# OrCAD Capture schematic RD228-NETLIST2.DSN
size A3
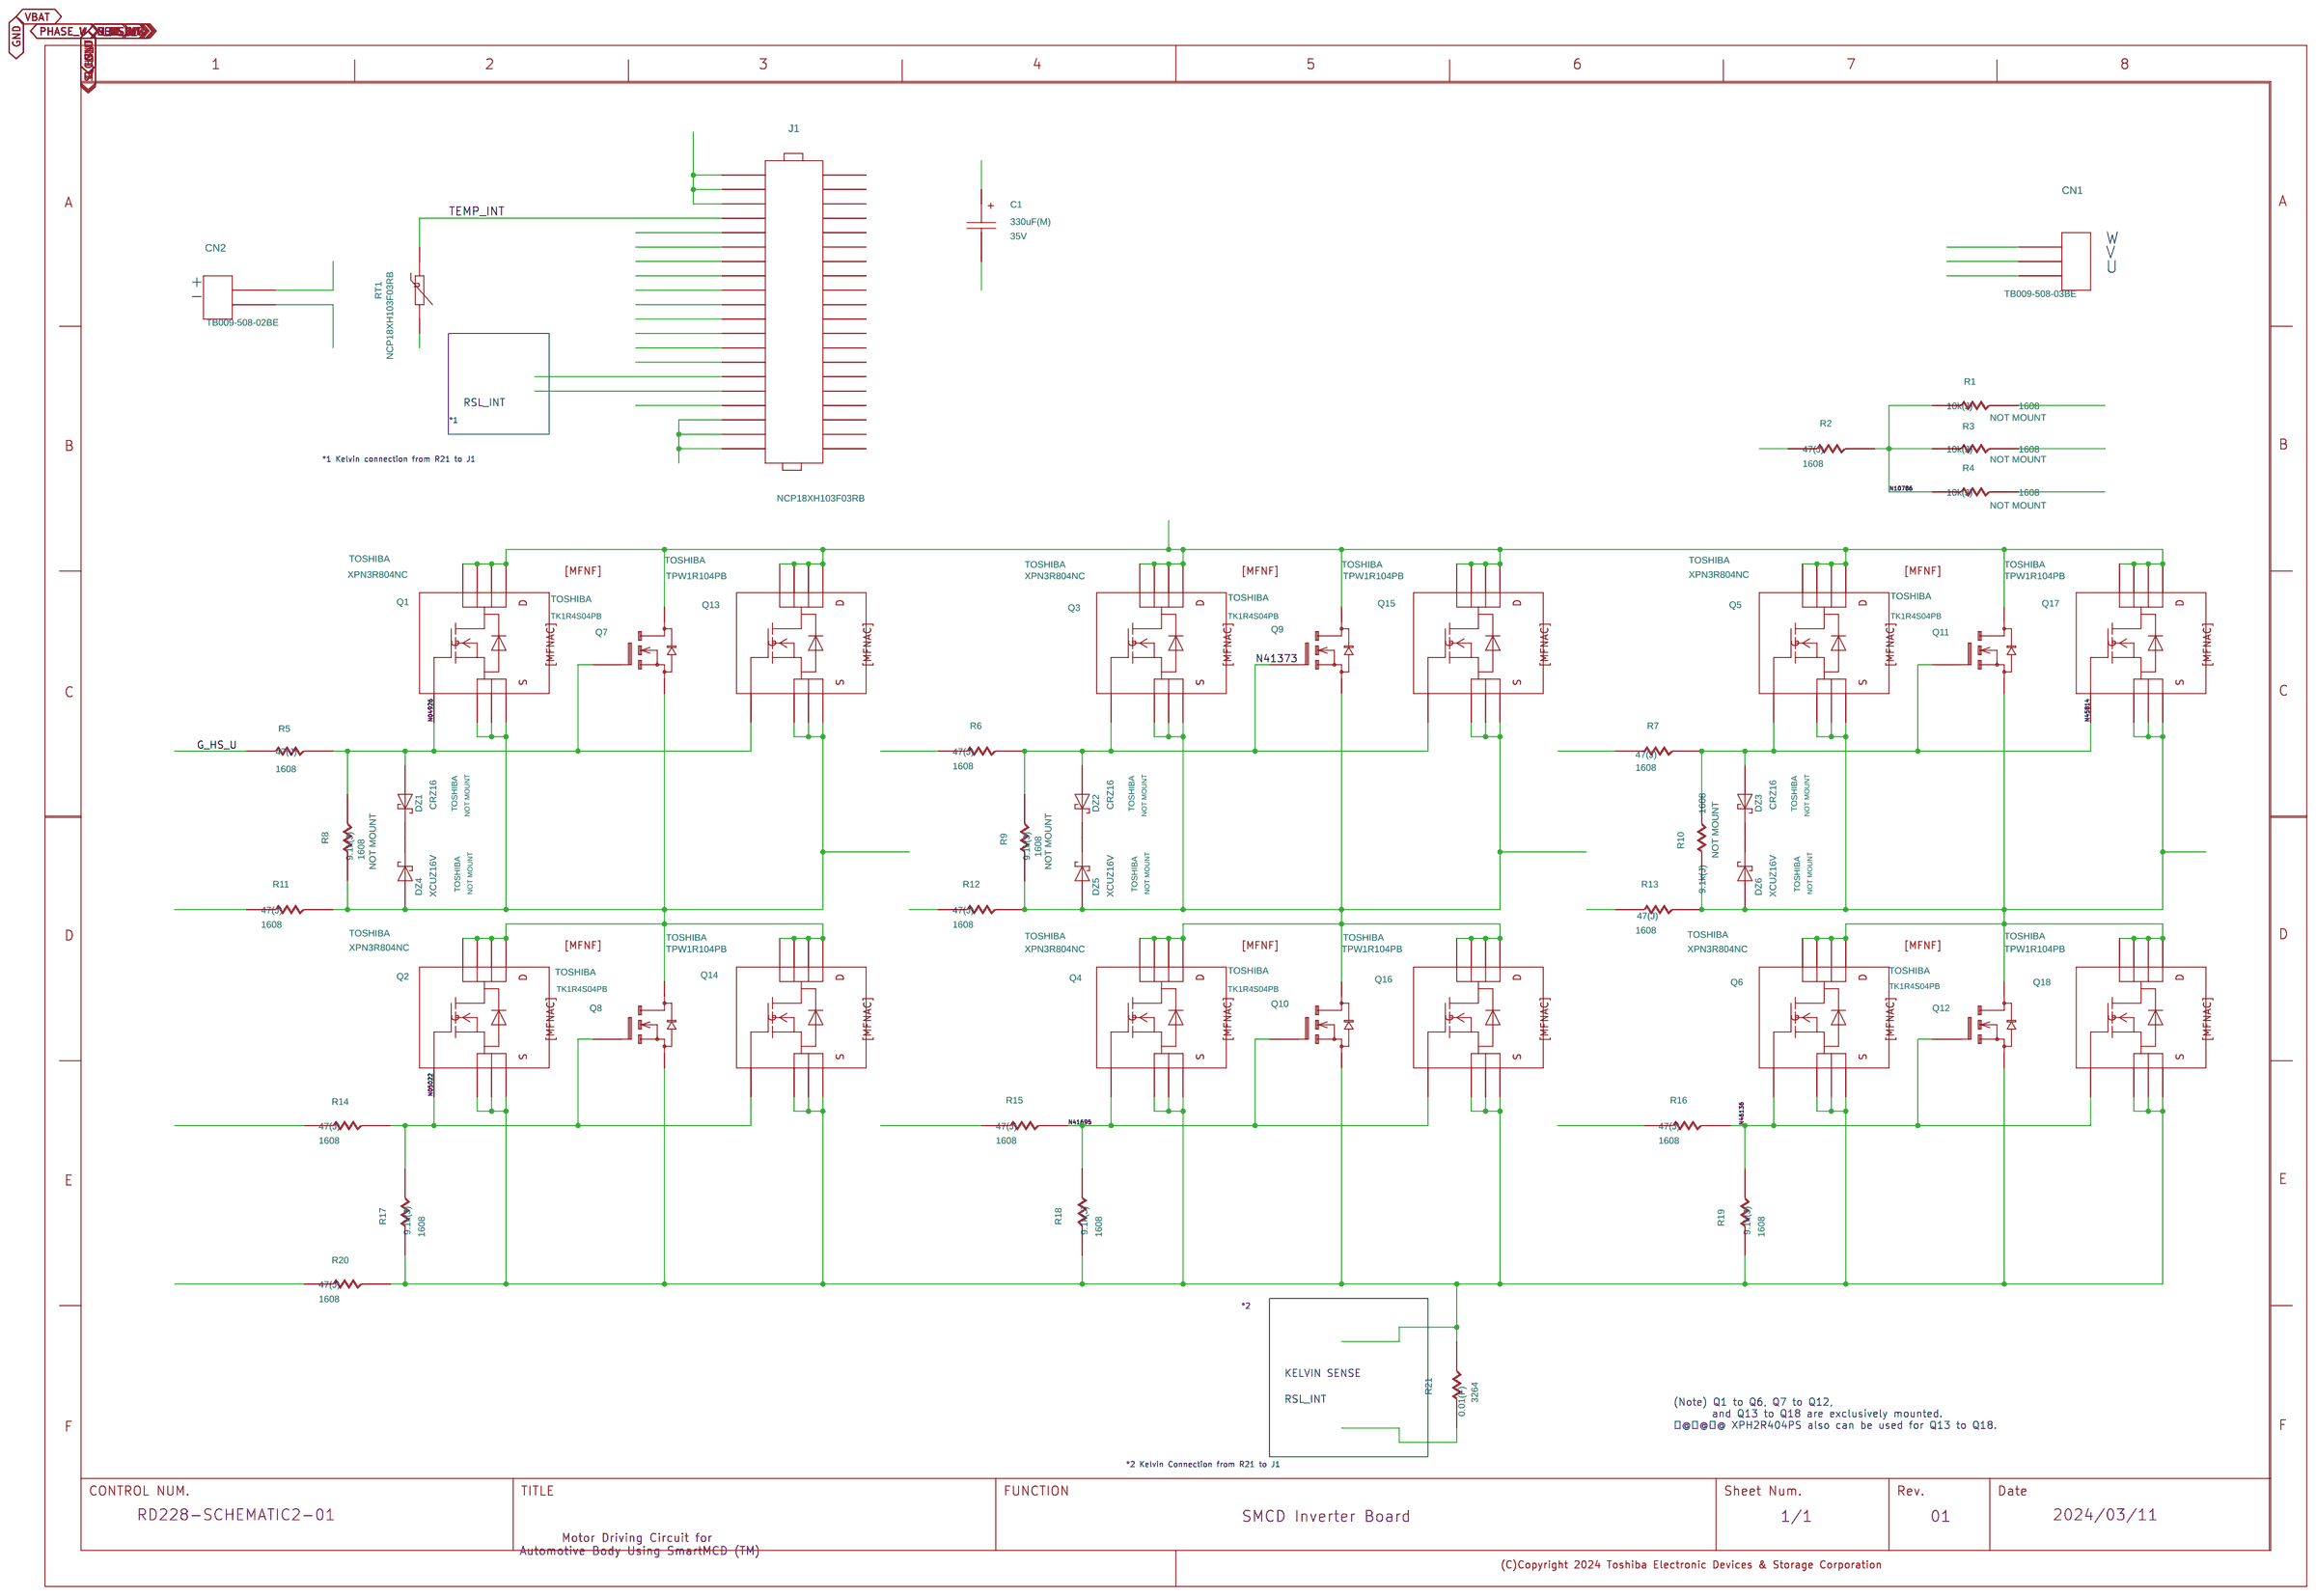
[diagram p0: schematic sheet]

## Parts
C1  CP
CN1  SCREW TERMINAL 3P
CN2  SCREW TERMINAL 2P
DZ1  SBD
DZ2  SBD
DZ3  SBD
DZ4  SBD
DZ5  SBD
DZ6  SBD
J1  CONN PCB 20x2
Q1  MFNAC
Q2  MFNAC
Q3  MFNAC
Q4  MFNAC
Q5  MFNAC
Q6  MFNAC
Q7  MFNF
Q8  MFNF
Q9  MFNF
Q10  MFNF
Q11  MFNF
Q12  MFNF
Q13  MFNAC
Q14  MFNAC
Q15  MFNAC
Q16  MFNAC
Q17  MFNAC
Q18  MFNAC
R1  R
R2  R
R3  R
R4  R
R5  R
R6  R
R7  R
R8  R
R9  R
R10  R
R11  R
R12  R
R13  R
R14  R
R15  R
R16  R
R17  R
R18  R
R19  R
R20  R
R21  R
RT1  VARA
U3  WAKU_DEF100

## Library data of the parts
C1 = CP: CAPACITANCETOLE: M; CDMASTERCADCELG: DC213N; CHIPSIZE: D35xL30; COMP: PRT_4; COMPONENTNAME: CP_CP; COMPONENTTYPE: 4; FNLEADFREETHET1GT2GMCTH1: 9_N_N; GCOUNT: 1; INSTANCENAME: INS16733; LAYOUTNAME: Z-4fe26e2d-0314-4a28-872c-3bd199d55978.cmp38; MAKER: RUBYCON; MAXGCOUNT: 1; NOMINALCAPACITA: 330u; OUMECLASSIFICATION: ƒAƒ‹ƒ~“d‰ðƒRƒ“ƒfƒ“ƒT; OUMEMAKER: SIT ƒ‹ƒrƒRƒ“; OUMEMAKERKATAMEI: 450MXC330M35X40; OUMEPARTTYPE: C; QUADMODEL: CON_330U; RATEDVOLTAGE: 450; SIZECODESMD: DIP; VAL1: 330uF(M); VAL2: 35V; VAL3: EEE-FN1V331UP; VAL4: Panasonic
CN1 = CON3: COMPONENTNAME: CON3_CON3; COMPONENTTYPE: 4; INSTANCENAME: INS12037; LAYOUTNAME: Z-4fe26e2d-0314-4a28-872c-3bd199d55978.cmp14; VAL3: TB009-508-03BE; VAL4: CUI Devices
CN2 = CON2: COMP: TB009-508-02BE; COMPONENTNAME: CON2_CON2; COMPONENTTYPE: 4; INSTANCENAME: INS65872; LAYOUTNAME: Z-4fe26e2d-0314-4a28-872c-3bd199d55978.cmp16; VAL4: CUI Devices
DZ1-DZ3 = SBD: AUTHOR: ikeda-k; COMPONENTKIND: 0; COMPONENTNAME: SBD_SBD; COMPONENTTYPE: 4; DATE: 2003/02/07; INSTANCENAME: INS75512; MAKER: TOSHIBA; NOTMOUNT: NOT MOUNT; NUMBER DEVICES IN PACKAGE: 1; PIN NAMES ROTATE: True; PIN NAMES VISIBLE: False; PIN NUMBERS VISIBLE: True; TIME: 14:49:55; UPDATEDATE: 2006/10/04; UPDATETIME: 08:16:22; UPDATEUSER: fukuda-y; USERCOMPTEXT3: TOSHIBA; VAL3: CRZ16; VAL4: TOSHIBA
DZ4-DZ6 = SBD: AUTHOR: ikeda-k; COMPONENTKIND: 0; COMPONENTNAME: SBD_SBD; COMPONENTTYPE: 4; DATE: 2003/02/07; INSTANCENAME: INS75524; MAKER: TOSHIBA; NOTMOUNT: NOT MOUNT; NUMBER DEVICES IN PACKAGE: 1; PIN NAMES ROTATE: True; PIN NAMES VISIBLE: False; PIN NUMBERS VISIBLE: True; TIME: 14:49:55; UPDATEDATE: 2006/10/04; UPDATETIME: 08:16:22; UPDATEUSER: fukuda-y; USERCOMPTEXT3: TOSHIBA; VAL3: XCUZ16V; VAL4: TOSHIBA
J1 = CONN_PCB_20X2_0: COMP: NCP18XH103F03RB; COMPONENTNAME: CONN_PCB_20x2_0_CONN_PCB_20x2_0; COMPONENTTYPE: 4; INSTANCENAME: INS11476; LAYOUTNAME: Z-4fe26e2d-0314-4a28-872c-3bd199d55978.cmp27; UPDATEDATE: 2024/2/16; UPDATETIME: 13:16:52; VAL3: 7-534206-0; VAL4: TE Connectivity
Q1 = MFNAC: COMP: PRT_67; COMPONENTNAME: MFNAC_MFNAC; COMPONENTTYPE: 4; INSTANCENAME: INS28653; LAYOUTNAME: Z-4fe26e2d-0314-4a28-872c-3bd199d55978.cmp44; MAKER: TOSHIBA; USERCOMPTEXT3: TOSHIBA; VAL3: XPN3R804NC; VAL4: TOSHIBA
Q2 = MFNAC: COMP: PRT_67; COMPONENTNAME: MFNAC_MFNAC; COMPONENTTYPE: 4; INSTANCENAME: INS31297; LAYOUTNAME: Z-4fe26e2d-0314-4a28-872c-3bd199d55978.cmp3; MAKER: TOSHIBA; USERCOMPTEXT3: TOSHIBA; VAL3: XPN3R804NC; VAL4: TOSHIBA
Q3 = MFNAC: COMP: PRT_67; COMPONENTNAME: MFNAC_MFNAC; COMPONENTTYPE: 4; INSTANCENAME: INS41315; LAYOUTNAME: Z-4fe26e2d-0314-4a28-872c-3bd199d55978.cmp10; MAKER: TOSHIBA; USERCOMPTEXT3: TOSHIBA; VAL3: XPN3R804NC; VAL4: TOSHIBA
Q4 = MFNAC: COMP: PRT_67; COMPONENTNAME: MFNAC_MFNAC; COMPONENTTYPE: 4; INSTANCENAME: INS41637; LAYOUTNAME: Z-4fe26e2d-0314-4a28-872c-3bd199d55978.cmp23; MAKER: TOSHIBA; USERCOMPTEXT3: TOSHIBA; VAL3: XPN3R804NC; VAL4: TOSHIBA
Q5 = MFNAC: COMP: PRT_67; COMPONENTNAME: MFNAC_MFNAC; COMPONENTTYPE: 4; INSTANCENAME: INS45756; LAYOUTNAME: Z-4fe26e2d-0314-4a28-872c-3bd199d55978.cmp8; MAKER: TOSHIBA; USERCOMPTEXT3: TOSHIBA; VAL3: XPN3R804NC; VAL4: TOSHIBA
Q6 = MFNAC: COMP: PRT_67; COMPONENTNAME: MFNAC_MFNAC; COMPONENTTYPE: 4; INSTANCENAME: INS46078; LAYOUTNAME: Z-4fe26e2d-0314-4a28-872c-3bd199d55978.cmp21; MAKER: TOSHIBA; USERCOMPTEXT3: TOSHIBA; VAL3: XPN3R804NC; VAL4: TOSHIBA
Q7 = MFNF: COMPONENTNAME: MFNF_MFNF; COMPONENTTYPE: 4; INSTANCENAME: INS28533; LAYOUTNAME: Z-4fe26e2d-0314-4a28-872c-3bd199d55978.cmp32; MAKER: TOSHIBA; USERCOMPTEXT3: TOSHIBA; VAL3: TK1R4S04PB; VAL4: TOSHIBA
Q8 = MFNF: COMP: PRT_9; COMPONENTNAME: MFNF_MFNF; COMPONENTTYPE: 4; INSTANCENAME: INS31341; LAYOUTNAME: Z-4fe26e2d-0314-4a28-872c-3bd199d55978.cmp20; MAKER: TOSHIBA; USERCOMPTEXT3: TOSHIBA; VAL3: TK1R4S04PB; VAL4: TOSHIBA
Q9 = MFNF: COMP: PRT_9; COMPONENTNAME: MFNF_MFNF; COMPONENTTYPE: 4; INSTANCENAME: INS41359; LAYOUTNAME: Z-4fe26e2d-0314-4a28-872c-3bd199d55978.cmp31; MAKER: TOSHIBA; USERCOMPTEXT3: TOSHIBA; VAL3: TK1R4S04PB; VAL4: TOSHIBA
Q10 = MFNF: COMP: PRT_9; COMPONENTNAME: MFNF_MFNF; COMPONENTTYPE: 4; INSTANCENAME: INS41681; LAYOUTNAME: Z-4fe26e2d-0314-4a28-872c-3bd199d55978.cmp40; MAKER: TOSHIBA; USERCOMPTEXT3: TOSHIBA; VAL3: TK1R4S04PB; VAL4: TOSHIBA
Q11 = MFNF: COMP: PRT_9; COMPONENTNAME: MFNF_MFNF; COMPONENTTYPE: 4; INSTANCENAME: INS45800; LAYOUTNAME: Z-4fe26e2d-0314-4a28-872c-3bd199d55978.cmp29; MAKER: TOSHIBA; USERCOMPTEXT3: TOSHIBA; VAL3: TK1R4S04PB; VAL4: TOSHIBA
Q12 = MFNF: COMP: PRT_9; COMPONENTNAME: MFNF_MFNF; COMPONENTTYPE: 4; INSTANCENAME: INS46122; LAYOUTNAME: Z-4fe26e2d-0314-4a28-872c-3bd199d55978.cmp39; MAKER: TOSHIBA; USERCOMPTEXT3: TOSHIBA; VAL3: TK1R4S04PB; VAL4: TOSHIBA
Q13 = MFNAC: COMPCOMMENT: XPH2R404PS; COMPONENTNAME: MFNAC_MFNAC; COMPONENTTYPE: 4; INSTANCENAME: INS28724; LAYOUTNAME: Z-4fe26e2d-0314-4a28-872c-3bd199d55978.cmp30; MAKER: TOSHIBA; USERCOMPTEXT3: TOSHIBA; VAL3: TPW1R104PB; VAL4: TOSHIBA
Q14 = MFNAC: COMP: PRT_67; COMPCOMMENT: XPH2R404PS; COMPONENTNAME: MFNAC_MFNAC; COMPONENTTYPE: 4; INSTANCENAME: INS31319; LAYOUTNAME: Z-4fe26e2d-0314-4a28-872c-3bd199d55978.cmp12; MAKER: TOSHIBA; USERCOMPTEXT3: TOSHIBA; VAL3: TPW1R104PB; VAL4: TOSHIBA
Q15 = MFNAC: COMP: PRT_67; COMPCOMMENT: XPH2R404PS; COMPONENTNAME: MFNAC_MFNAC; COMPONENTTYPE: 4; INSTANCENAME: INS41337; LAYOUTNAME: Z-4fe26e2d-0314-4a28-872c-3bd199d55978.cmp26; MAKER: TOSHIBA; USERCOMPTEXT3: TOSHIBA; VAL3: TPW1R104PB; VAL4: TOSHIBA
Q16 = MFNAC: COMP: PRT_67; COMPCOMMENT: XPH2R404PS; COMPONENTNAME: MFNAC_MFNAC; COMPONENTTYPE: 4; INSTANCENAME: INS41659; LAYOUTNAME: Z-4fe26e2d-0314-4a28-872c-3bd199d55978.cmp34; MAKER: TOSHIBA; USERCOMPTEXT3: TOSHIBA; VAL3: TPW1R104PB; VAL4: TOSHIBA
Q17 = MFNAC: COMP: PRT_67; COMPCOMMENT: XPH2R404PS; COMPONENTNAME: MFNAC_MFNAC; COMPONENTTYPE: 4; INSTANCENAME: INS45778; LAYOUTNAME: Z-4fe26e2d-0314-4a28-872c-3bd199d55978.cmp22; MAKER: TOSHIBA; USERCOMPTEXT3: TOSHIBA; VAL3: TPW1R104PB; VAL4: TOSHIBA
Q18 = MFNAC: COMP: PRT_67; COMPCOMMENT: XPH2R404PS; COMPONENTNAME: MFNAC_MFNAC; COMPONENTTYPE: 4; INSTANCENAME: INS46100; LAYOUTNAME: Z-4fe26e2d-0314-4a28-872c-3bd199d55978.cmp33; MAKER: TOSHIBA; USERCOMPTEXT3: TOSHIBA; VAL3: TPW1R104PB; VAL4: TOSHIBA
R1 = R: ADSMODELNAME: s_RL1632H_R001_JN; CDMASTERCADCELG: KC0020; CHIPSIZE: 3216; COMP: PRT_5; COMPONENTNAME: R_R; COMPONENTTYPE: 4; FNLEADFREETHET1GT2GMCTH1: N_N_N; GCOUNT: 1; INSTANCENAME: INS10722; LAYOUTNAME: Z-4fe26e2d-0314-4a28-872c-3bd199d55978.cmp9; MAKER: KOA; MAXGCOUNT: 1; MOUNTINGFORMSMD: SMD; NOMINALRESISTAN: 1m; NOTMOUNT: NOT MOUNT; OUMECLASSIFICATION: \ÊÀpÅèïRí; OUMEMAKER: SSM iHÆ; OUMEMAKERKATAMEI: RL1632H-R001-JN; POWERRATING: 500m; QUADMODEL: RES_1M; RESISTANCETOLER: J; SIZECODESMD: 1608; VAL1: 10k(J); VAL2: 0.1W; VAL3: RK73B1ETTP103J; VAL4: KOA
R2 = R: ADSMODELNAME: s_RL1632H_R001_JN; CDMASTERCADCELG: KC0020; CHIPSIZE: 3216; COMP: PRT_5; COMPONENTNAME: R_R; COMPONENTTYPE: 4; FNLEADFREETHET1GT2GMCTH1: N_N_N; GCOUNT: 1; INSTANCENAME: INS10855; LAYOUTNAME: Z-4fe26e2d-0314-4a28-872c-3bd199d55978.cmp28; MAKER: KOA; MAXGCOUNT: 1; MOUNTINGFORMSMD: SMD; NOMINALRESISTAN: 1m; OUMECLASSIFICATION: \ÊÀpÅèïRí; OUMEMAKER: SSM iHÆ; OUMEMAKERKATAMEI: RL1632H-R001-JN; POWERRATING: 500m; QUADMODEL: RES_1M; RESISTANCETOLER: J; SIZECODESMD: 1608; VAL1: 47(J); VAL2: 0.1W; VAL3: RK73B1ETTP470J; VAL4: KOA
R3 = R: ADSMODELNAME: s_RL1632H_R001_JN; CDMASTERCADCELG: KC0020; CHIPSIZE: 3216; COMP: PRT_5; COMPONENTNAME: R_R; COMPONENTTYPE: 4; FNLEADFREETHET1GT2GMCTH1: N_N_N; GCOUNT: 1; INSTANCENAME: INS10744; LAYOUTNAME: Z-4fe26e2d-0314-4a28-872c-3bd199d55978.cmp24; MAKER: KOA; MAXGCOUNT: 1; MOUNTINGFORMSMD: SMD; NOMINALRESISTAN: 1m; NOTMOUNT: NOT MOUNT; OUMECLASSIFICATION: \ÊÀpÅèïRí; OUMEMAKER: SSM iHÆ; OUMEMAKERKATAMEI: RL1632H-R001-JN; POWERRATING: 500m; QUADMODEL: RES_1M; RESISTANCETOLER: J; SIZECODESMD: 1608; VAL1: 10k(J); VAL2: 0.1W; VAL3: RK73B1ETTP103J; VAL4: KOA
R4 = R: ADSMODELNAME: s_RL1632H_R001_JN; CDMASTERCADCELG: KC0020; CHIPSIZE: 3216; COMP: PRT_5; COMPONENTNAME: R_R; COMPONENTTYPE: 4; FNLEADFREETHET1GT2GMCTH1: N_N_N; GCOUNT: 1; INSTANCENAME: INS10766; LAYOUTNAME: Z-4fe26e2d-0314-4a28-872c-3bd199d55978.cmp35; MAKER: KOA; MAXGCOUNT: 1; MOUNTINGFORMSMD: SMD; NOMINALRESISTAN: 1m; NOTMOUNT: NOT MOUNT; OUMECLASSIFICATION: \ÊÀpÅèïRí; OUMEMAKER: SSM iHÆ; OUMEMAKERKATAMEI: RL1632H-R001-JN; POWERRATING: 500m; QUADMODEL: RES_1M; RESISTANCETOLER: J; SIZECODESMD: 1608; VAL1: 10k(J); VAL2: 0.1W; VAL3: RK73B1ETTP103J; VAL4: KOA
R5 = R: ADSMODELNAME: s_RL1632H_R001_JN; CDMASTERCADCELG: KC0020; CHIPSIZE: 3216; COMP: PRT_5; COMPONENTNAME: R_R; COMPONENTTYPE: 4; FNLEADFREETHET1GT2GMCTH1: N_N_N; GCOUNT: 1; INSTANCENAME: INS6200; LAYOUTNAME: Z-4fe26e2d-0314-4a28-872c-3bd199d55978.cmp25; MAKER: KOA; MAXGCOUNT: 1; MOUNTINGFORMSMD: SMD; NOMINALRESISTAN: 1m; OUMECLASSIFICATION: \ÊÀpÅèïRí; OUMEMAKER: SSM iHÆ; OUMEMAKERKATAMEI: RL1632H-R001-JN; POWERRATING: 500m; QUADMODEL: RES_1M; RESISTANCETOLER: J; SIZECODESMD: 1608; VAL1: 47(J); VAL2: 0.1W; VAL3: RK73B1JTTD470J; VAL4: KOA
R6 = R: ADSMODELNAME: s_RL1632H_R001_JN; CDMASTERCADCELG: KC0020; CHIPSIZE: 3216; COMP: PRT_5; COMPONENTNAME: R_R; COMPONENTTYPE: 4; FNLEADFREETHET1GT2GMCTH1: N_N_N; GCOUNT: 1; INSTANCENAME: INS41415; LAYOUTNAME: Z-4fe26e2d-0314-4a28-872c-3bd199d55978.cmp5; MAKER: KOA; MAXGCOUNT: 1; MOUNTINGFORMSMD: SMD; NOMINALRESISTAN: 1m; OUMECLASSIFICATION: \ÊÀpÅèïRí; OUMEMAKER: SSM iHÆ; OUMEMAKERKATAMEI: RL1632H-R001-JN; POWERRATING: 500m; QUADMODEL: RES_1M; RESISTANCETOLER: J; SIZECODESMD: 1608; VAL1: 47(J); VAL2: 0.1W; VAL3: RK73B1JTTD470J; VAL4: KOA
R7 = R: ADSMODELNAME: s_RL1632H_R001_JN; CDMASTERCADCELG: KC0020; CHIPSIZE: 3216; COMPONENTNAME: R_R; COMPONENTTYPE: 4; FNLEADFREETHET1GT2GMCTH1: N_N_N; GCOUNT: 1; INSTANCENAME: INS45856; LAYOUTNAME: Z-4fe26e2d-0314-4a28-872c-3bd199d55978.cmp4; MAKER: KOA; MAXGCOUNT: 1; MOUNTINGFORMSMD: SMD; NOMINALRESISTAN: 1m; OUMECLASSIFICATION: \ÊÀpÅèïRí; OUMEMAKER: SSM iHÆ; OUMEMAKERKATAMEI: RL1632H-R001-JN; POWERRATING: 500m; QUADMODEL: RES_1M; RESISTANCETOLER: J; SIZECODESMD: 1608; VAL1: 47(J); VAL2: 0.1W; VAL3: RK73B1JTTD470J; VAL4: KOA
R8 = R: ADSMODELNAME: s_RK73B1JTTD103J@@; CDMASTERCADCELG: KC0133; CHIPSIZE: 1608; COMP: PRT_8; COMPONENTNAME: R_R; COMPONENTTYPE: 4; FNLEADFREETHET1GT2GMCTH1: N_N_N; GCOUNT: 1; INSTANCENAME: INS8565; LAYOUTNAME: Z-4fe26e2d-0314-4a28-872c-3bd199d55978.cmp43; MAKER: KOA; MAXGCOUNT: 1; MOUNTINGFORMSMD: SMD; NOMINALRESISTAN: 10K; NOTMOUNT: NOT MOUNT; OUMECLASSIFICATION: \ÊÀpÅèïRí; OUMEMAKER: KOA R[A; OUMEMAKERKATAMEI: RK73B1JTTD103J@@; POWERRATING: 100m; QUADMODEL: RES_10K; RESISTANCETOLER: J; SIZECODESMD: 1608; VAL1: 9.1k(J); VAL2: 0.1W; VAL3: RK73B1ETTP912J; VAL4: KOA
R9 = R: ADSMODELNAME: s_RK73B1JTTD103J@@; CDMASTERCADCELG: KC0133; CHIPSIZE: 1608; COMP: PRT_8; COMPONENTNAME: R_R; COMPONENTTYPE: 4; FNLEADFREETHET1GT2GMCTH1: N_N_N; GCOUNT: 1; INSTANCENAME: INS41505; LAYOUTNAME: Z-4fe26e2d-0314-4a28-872c-3bd199d55978.cmp1; MAKER: KOA; MAXGCOUNT: 1; MOUNTINGFORMSMD: SMD; NOMINALRESISTAN: 10K; NOTMOUNT: NOT MOUNT; OUMECLASSIFICATION: \ÊÀpÅèïRí; OUMEMAKER: KOA R[A; OUMEMAKERKATAMEI: RK73B1JTTD103J@@; POWERRATING: 100m; QUADMODEL: RES_10K; RESISTANCETOLER: J; SIZECODESMD: 1608; VAL1: 9.1k(J); VAL2: 0.1W; VAL3: RK73B1ETTP912J; VAL4: KOA
R10 = R: ADSMODELNAME: s_RK73B1JTTD103J@@; CDMASTERCADCELG: KC0133; CHIPSIZE: 1608; COMP: PRT_8; COMPONENTNAME: R_R; COMPONENTTYPE: 4; FNLEADFREETHET1GT2GMCTH1: N_N_N; GCOUNT: 1; INSTANCENAME: INS45946; LAYOUTNAME: Z-4fe26e2d-0314-4a28-872c-3bd199d55978.cmp48; MAKER: KOA; MAXGCOUNT: 1; MOUNTINGFORMSMD: SMD; NOMINALRESISTAN: 10K; NOTMOUNT: NOT MOUNT; OUMECLASSIFICATION: \ÊÀpÅèïRí; OUMEMAKER: KOA R[A; OUMEMAKERKATAMEI: RK73B1JTTD103J@@; POWERRATING: 100m; QUADMODEL: RES_10K; RESISTANCETOLER: J; SIZECODESMD: 1608; VAL1: 9.1k(J); VAL2: 0.1W; VAL3: RK73B1ETTP912J; VAL4: KOA
R11 = R: ADSMODELNAME: s_RL1632H_R001_JN; CDMASTERCADCELG: KC0020; CHIPSIZE: 3216; COMP: PRT_5; COMPONENTNAME: R_R; COMPONENTTYPE: 4; FNLEADFREETHET1GT2GMCTH1: N_N_N; GCOUNT: 1; INSTANCENAME: INS6356; LAYOUTNAME: Z-4fe26e2d-0314-4a28-872c-3bd199d55978.cmp51; MAKER: KOA; MAXGCOUNT: 1; MOUNTINGFORMSMD: SMD; NOMINALRESISTAN: 1m; OUMECLASSIFICATION: \ÊÀpÅèïRí; OUMEMAKER: SSM iHÆ; OUMEMAKERKATAMEI: RL1632H-R001-JN; POWERRATING: 500m; QUADMODEL: RES_1M; RESISTANCETOLER: J; SIZECODESMD: 1608; VAL1: 47(J); VAL2: 0.1W; VAL3: RK73B1JTTD470J; VAL4: KOA
R12 = R: ADSMODELNAME: s_RL1632H_R001_JN; CDMASTERCADCELG: KC0020; CHIPSIZE: 3216; COMP: PRT_5; COMPONENTNAME: R_R; COMPONENTTYPE: 4; FNLEADFREETHET1GT2GMCTH1: N_N_N; GCOUNT: 1; INSTANCENAME: INS41533; LAYOUTNAME: Z-4fe26e2d-0314-4a28-872c-3bd199d55978.cmp13; MAKER: KOA; MAXGCOUNT: 1; MOUNTINGFORMSMD: SMD; NOMINALRESISTAN: 1m; OUMECLASSIFICATION: \ÊÀpÅèïRí; OUMEMAKER: SSM iHÆ; OUMEMAKERKATAMEI: RL1632H-R001-JN; POWERRATING: 500m; QUADMODEL: RES_1M; RESISTANCETOLER: J; SIZECODESMD: 1608; VAL1: 47(J); VAL2: 0.1W; VAL3: RK73B1JTTD470J; VAL4: KOA
R13 = R: ADSMODELNAME: s_RL1632H_R001_JN; CDMASTERCADCELG: KC0020; CHIPSIZE: 3216; COMP: PRT_5; COMPONENTNAME: R_R; COMPONENTTYPE: 4; FNLEADFREETHET1GT2GMCTH1: N_N_N; GCOUNT: 1; INSTANCENAME: INS45984; LAYOUTNAME: Z-4fe26e2d-0314-4a28-872c-3bd199d55978.cmp18; MAKER: KOA; MAXGCOUNT: 1; MOUNTINGFORMSMD: SMD; NOMINALRESISTAN: 1m; OUMECLASSIFICATION: \ÊÀpÅèïRí; OUMEMAKER: SSM iHÆ; OUMEMAKERKATAMEI: RL1632H-R001-JN; POWERRATING: 500m; QUADMODEL: RES_1M; RESISTANCETOLER: J; SIZECODESMD: 1608; VAL1: 47(J); VAL2: 0.1W; VAL3: RK73B1JTTD470J; VAL4: KOA
R14 = R: ADSMODELNAME: s_RL1632H_R001_JN; CDMASTERCADCELG: KC0020; CHIPSIZE: 3216; COMP: PRT_5; COMPONENTNAME: R_R; COMPONENTTYPE: 4; FNLEADFREETHET1GT2GMCTH1: N_N_N; GCOUNT: 1; INSTANCENAME: INS5242; LAYOUTNAME: Z-4fe26e2d-0314-4a28-872c-3bd199d55978.cmp47; MAKER: KOA; MAXGCOUNT: 1; MOUNTINGFORMSMD: SMD; NOMINALRESISTAN: 1m; OUMECLASSIFICATION: \ÊÀpÅèïRí; OUMEMAKER: SSM iHÆ; OUMEMAKERKATAMEI: RL1632H-R001-JN; POWERRATING: 500m; QUADMODEL: RES_1M; RESISTANCETOLER: J; SIZECODESMD: 1608; VAL1: 47(J); VAL2: 0.1W; VAL3: RK73B1JTTD470J; VAL4: KOA
R15 = R: ADSMODELNAME: s_RL1632H_R001_JN; CDMASTERCADCELG: KC0020; CHIPSIZE: 3216; COMP: PRT_5; COMPONENTNAME: R_R; COMPONENTTYPE: 4; FNLEADFREETHET1GT2GMCTH1: N_N_N; GCOUNT: 1; INSTANCENAME: INS41737; LAYOUTNAME: Z-4fe26e2d-0314-4a28-872c-3bd199d55978.cmp15; MAKER: KOA; MAXGCOUNT: 1; MOUNTINGFORMSMD: SMD; NOMINALRESISTAN: 1m; OUMECLASSIFICATION: \ÊÀpÅèïRí; OUMEMAKER: SSM iHÆ; OUMEMAKERKATAMEI: RL1632H-R001-JN; POWERRATING: 500m; QUADMODEL: RES_1M; RESISTANCETOLER: J; SIZECODESMD: 1608; VAL1: 47(J); VAL2: 0.1W; VAL3: RK73B1JTTD470J; VAL4: KOA
R16 = R: ADSMODELNAME: s_RL1632H_R001_JN; CDMASTERCADCELG: KC0020; CHIPSIZE: 3216; COMP: PRT_5; COMPONENTNAME: R_R; COMPONENTTYPE: 4; FNLEADFREETHET1GT2GMCTH1: N_N_N; GCOUNT: 1; INSTANCENAME: INS46178; LAYOUTNAME: Z-4fe26e2d-0314-4a28-872c-3bd199d55978.cmp11; MAKER: KOA; MAXGCOUNT: 1; MOUNTINGFORMSMD: SMD; NOMINALRESISTAN: 1m; OUMECLASSIFICATION: \ÊÀpÅèïRí; OUMEMAKER: SSM iHÆ; OUMEMAKERKATAMEI: RL1632H-R001-JN; POWERRATING: 500m; QUADMODEL: RES_1M; RESISTANCETOLER: J; SIZECODESMD: 1608; VAL1: 47(J); VAL2: 0.1W; VAL3: RK73B1JTTD470J; VAL4: KOA
R17 = R: ADSMODELNAME: s_RK73B1JTTD103J@@; CDMASTERCADCELG: KC0133; CHIPSIZE: 1608; COMP: PRT_8; COMPONENTNAME: R_R; COMPONENTTYPE: 4; FNLEADFREETHET1GT2GMCTH1: N_N_N; GCOUNT: 1; INSTANCENAME: INS5742; LAYOUTNAME: Z-4fe26e2d-0314-4a28-872c-3bd199d55978.cmp46; MAKER: KOA; MAXGCOUNT: 1; MOUNTINGFORMSMD: SMD; NOMINALRESISTAN: 10K; OUMECLASSIFICATION: \ÊÀpÅèïRí; OUMEMAKER: KOA R[A; OUMEMAKERKATAMEI: RK73B1JTTD103J@@; POWERRATING: 100m; QUADMODEL: RES_10K; RESISTANCETOLER: J; SIZECODESMD: 1608; VAL1: 9.1k(J); VAL2: 0.1W; VAL3: RK73B1ETTP912J; VAL4: KOA
R18 = R: ADSMODELNAME: s_RK73B1JTTD103J@@; CDMASTERCADCELG: KC0133; CHIPSIZE: 1608; COMP: PRT_8; COMPONENTNAME: R_R; COMPONENTTYPE: 4; FNLEADFREETHET1GT2GMCTH1: N_N_N; GCOUNT: 1; INSTANCENAME: INS41807; LAYOUTNAME: Z-4fe26e2d-0314-4a28-872c-3bd199d55978.cmp50; MAKER: KOA; MAXGCOUNT: 1; MOUNTINGFORMSMD: SMD; NOMINALRESISTAN: 10K; OUMECLASSIFICATION: \ÊÀpÅèïRí; OUMEMAKER: KOA R[A; OUMEMAKERKATAMEI: RK73B1JTTD103J@@; POWERRATING: 100m; QUADMODEL: RES_10K; RESISTANCETOLER: J; SIZECODESMD: 1608; VAL1: 9.1k(J); VAL2: 0.1W; VAL3: RK73B1ETTP912J; VAL4: KOA
R19 = R: ADSMODELNAME: s_RK73B1JTTD103J@@; CDMASTERCADCELG: KC0133; CHIPSIZE: 1608; COMP: PRT_8; COMPONENTNAME: R_R; COMPONENTTYPE: 4; FNLEADFREETHET1GT2GMCTH1: N_N_N; GCOUNT: 1; INSTANCENAME: INS46240; LAYOUTNAME: Z-4fe26e2d-0314-4a28-872c-3bd199d55978.cmp45; MAKER: KOA; MAXGCOUNT: 1; MOUNTINGFORMSMD: SMD; NOMINALRESISTAN: 10K; OUMECLASSIFICATION: \ÊÀpÅèïRí; OUMEMAKER: KOA R[A; OUMEMAKERKATAMEI: RK73B1JTTD103J@@; POWERRATING: 100m; QUADMODEL: RES_10K; RESISTANCETOLER: J; SIZECODESMD: 1608; VAL1: 9.1k(J); VAL2: 0.1W; VAL3: RK73B1ETTP912J; VAL4: KOA
R20 = R: ADSMODELNAME: s_RL1632H_R001_JN; CDMASTERCADCELG: KC0020; CHIPSIZE: 3216; COMP: PRT_5; COMPONENTNAME: R_R; COMPONENTTYPE: 4; FNLEADFREETHET1GT2GMCTH1: N_N_N; GCOUNT: 1; INSTANCENAME: INS78910; LAYOUTNAME: Z-4fe26e2d-0314-4a28-872c-3bd199d55978.cmp19; MAKER: KOA; MAXGCOUNT: 1; MOUNTINGFORMSMD: SMD; NOMINALRESISTAN: 1m; OUMECLASSIFICATION: \ÊÀpÅèïRí; OUMEMAKER: SSM iHÆ; OUMEMAKERKATAMEI: RL1632H-R001-JN; POWERRATING: 500m; QUADMODEL: RES_1M; RESISTANCETOLER: J; SIZECODESMD: 1608; VAL1: 47(J); VAL2: 0.1W; VAL3: RK73B1ETTP470J; VAL4: KOA
R21 = R: ADSMODELNAME: s_RK73B1JTTD103J@@; CDMASTERCADCELG: KC0133; CHIPSIZE: 1608; COMP: PRT_8; COMPONENTNAME: R_R; COMPONENTTYPE: 4; FNLEADFREETHET1GT2GMCTH1: N_N_N; GCOUNT: 1; INSTANCENAME: INS10514; LAYOUTNAME: Z-4fe26e2d-0314-4a28-872c-3bd199d55978.cmp6; MAKER: KOA; MAXGCOUNT: 1; MOUNTINGFORMSMD: SMD; NOMINALRESISTAN: 10K; OUMECLASSIFICATION: \ÊÀpÅèïRí; OUMEMAKER: KOA R[A; OUMEMAKERKATAMEI: RK73B1JTTD103J@@; POWERRATING: 100m; QUADMODEL: RES_10K; RESISTANCETOLER: J; SIZECODESMD: 3264; VAL1: 0.01(F); VAL2: 2W; VAL3: PRL3264-R010-F-T1; VAL4: SSM
RT1 = VARA_0: CDMASTERCADCELG: KC0008; COMP: PRT_37; COMPONENTNAME: VARA_0_VARA_0; COMPONENTTYPE: 4; FNLEADFREETHET1GT2GMCTH1: N_N_N; GCOUNT: 1; INSTANCENAME: INS13125; LAYOUTNAME: Z-4fe26e2d-0314-4a28-872c-3bd199d55978.cmp2; MAKER: NIPPON CHEMICON; MAXGCOUNT: 1; MOUNTINGFORMSMD: SMD; OUMECLASSIFICATION: ƒoƒŠƒXƒ^; OUMEMAKER: TDK ‚s‚c‚j; OUMEMAKERKATAMEI: AVR-M1608C220KT6AB; OUMEPARTTYPE: RV; RATEDVOLTAGE: 0; VAL1: NTC 10k; VAL2: R1005; VAL3: NCP18XH103F03RB; VAL4: TDK
U3 = WAKU_DEF100: COMPONENTTYPE: 0; DATE: 2024/03/11; DESIGNED: TOSHIBA; DRAWINGNUMBER: RD228-SCHEMATIC2-01; FUNCTION: SMCD Inverter Board; INSTANCENAME: INS88674; LAYOUTNAME: Z-4fe26e2d-0314-4a28-872c-3bd199d55978.cmp49; NOTMOUNT: MOUNT; PAGENUMBER: 1/1; REVISION: 01; SHEETNUMBER: 1/1; TITLE: Motor Driving Circuit for / Automotive Body Using SmartMCD (TM); UPDATEDATE: 2024/2/16; UPDATETIME: 13:16:51

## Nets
GND: C1.1 CN2.2 J1.31 J1.35 J1.37 J1.39 R21.1 RT1.2
VBAT: C1.2 CN2.1 J1.1 J1.3 J1.5 Q1.5 Q1.6 Q1.7 Q1.8 Q3.5 Q3.6 Q3.7 Q3.8 Q5.5 Q5.6 Q5.7 Q5.8 Q7.D Q9.D Q11.D Q13.5 Q13.6 Q13.7 Q13.8 Q15.5 Q15.6 Q15.7 Q15.8 Q17.5 Q17.6 Q17.7 Q17.8
COM_INT: J1.33 R2.1
G_HS_U: J1.25 R5.1
G_HS_V: J1.19 R6.1
G_HS_W: J1.13 R7.1
G_LS_U: J1.21 R14.1
G_LS_V: J1.15 R15.1
G_LS_W: J1.9 R16.1
M_U: J1.23 R11.1
M_V: J1.17 R12.1
M_W: J1.11 R13.1
PHASE_U: CN1.3 DZ4.A Q1.1 Q1.2 Q1.3 Q2.5 Q2.6 Q2.7 Q2.8 Q7.S Q8.D Q13.1 Q13.2 Q13.3 Q14.5 Q14.6 Q14.7 Q14.8 R4.2 R8.1 R11.2
PHASE_V: CN1.2 DZ5.A Q3.1 Q3.2 Q3.3 Q4.5 Q4.6 Q4.7 Q4.8 Q9.S Q10.D Q15.1 Q15.2 Q15.3 Q16.5 Q16.6 Q16.7 Q16.8 R3.2 R9.1 R12.2
PHASE_W: CN1.1 DZ6.A Q5.1 Q5.2 Q5.3 Q6.5 Q6.6 Q6.7 Q6.8 Q11.S Q12.D Q17.1 Q17.2 Q17.3 Q18.5 Q18.6 Q18.7 Q18.8 R1.2 R10.1 R13.2
RSH_INT: J1.29 Q2.1 Q2.2 Q2.3 Q4.1 Q4.2 Q4.3 Q6.1 Q6.2 Q6.3 Q8.S Q10.S Q12.S Q14.1 Q14.2 Q14.3 Q16.1 Q16.2 Q16.3 Q18.1 Q18.2 Q18.3 R17.1 R18.2 R19.1 R20.2 R21.2
SLC_INT: J1.27 R20.1
TEMP_INT: J1.7 RT1.1
N02276: DZ1.C DZ4.C
N02277: DZ2.C DZ5.C
N02278: DZ3.C DZ6.C
N04926: DZ1.A Q1.4 Q7.G Q13.4 R5.2 R8.2
N05022: Q2.4 Q8.G Q14.4 R14.2 R17.2
N10786: R1.1 R2.2 R3.1 R4.1
N41373: DZ2.A Q3.4 Q9.G Q15.4 R6.2 R9.2
N41695: Q4.4 Q10.G Q16.4 R15.2 R18.1
N45814: DZ3.A Q5.4 Q11.G Q17.4 R7.2 R10.2
N46136: Q6.4 Q12.G Q18.4 R16.2 R19.2

Not connected (* = marked no-connect by the designer): J1 2 4 6 8 10 12 14 16 18 20 22 24 26 28 30 32 34 36 38 40

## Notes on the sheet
- W
- V
- U
- +
- -
- RSL_INT
- *1
- *1 Kelvin connection from R21 to J1
- *2
- KELVIN SENSE
- RSL_INT
- (Note) Q1 to Q6, Q7 to Q12,
         and Q13 to Q18 are exclusively mounted.
  @@@ XPH2R404PS also can be used for Q13 to Q18.
- *2 Kelvin Connection from R21 to J1
